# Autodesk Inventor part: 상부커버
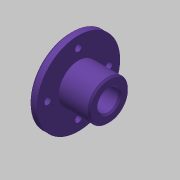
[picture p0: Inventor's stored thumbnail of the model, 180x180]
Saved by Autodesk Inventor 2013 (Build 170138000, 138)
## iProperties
Created: 2015-09
Part Number: 상부커버
Material: 알루미늄 6061
Document SubType Name: Modeling
Designer: mduedu
Density: 1 g/cm^3
Author: mduedu
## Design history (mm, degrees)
sketch "스케치1"
  geometry: L1 (-12.5, 0)-(12.5, 0); L2 (-12.5, 0)-(-12.5, 27); L3 (-12.5, 27)-(-7.5, 27); L4 (-7.5, 27)-(-7.5, 13); L5 (-7.5, 13)-(12.5, 13); L6 (12.5, 13)-(12.5, 0); 2 further points
  constraints: 12 end point, 2 parallel, 2 perpendicular, 1 coincident, 1 horizontal, 1 midpoint, 1 vertical
  dimensions: "d0" = 25 distance of L1.start L1.end; "d2" = 5 distance of L2.end L3.end; "d3" = 26 diameter of L5 L1; "d4" = 54 diameter of L3 L1
revolve "회전1" sketch "스케치1" stored, may be unused: angle "d5" = 90 deg
hole "구멍1" diameter "d8" = 14; stored, may be unused: countersink angle "d12" = 90 deg, drill point angle "d14" = 118 deg; dims "d6" = 10, "d7" = 10, "d9" = 6, "d10" = 4, "d11" = 2, "d13" = 8
chamfer "모따기1" distance "d15" = 1; stored, may be unused: second distance "d16" = 2, angle "d17" = 45 deg
chamfer "모따기2" distance "d18" = 1; stored, may be unused: second distance "d19" = 2, angle "d20" = 45 deg
sketch "스케치2" dims "d21" = 40
  geometry: 6 further points
  constraints: 2 vertical alignment, 1 coincident, 7 other
  dimensions: "d25" = 360 deg dimension on point (0, 0) point (0, 20) (derived)
sketch "스케치3"
  geometry: 4 further points
hole "구멍2" sketch "스케치3" at (0, 20), (-20, 0), (20, 0), (0, -20) diameter "d27" = 4.5; stored, may be unused: countersink angle "d31" = 90 deg, drill point angle "d33" = 0 deg; dims "d28" = 6, "d29" = 4, "d30" = 2, "d32" = 8
chamfer "모따기3" distance "d34" = 1; stored, may be unused: second distance "d35" = 2, angle "d36" = 45 deg
node "솔리드1"
